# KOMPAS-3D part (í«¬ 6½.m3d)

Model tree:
1. Эскиз:1
2. Операция выдавливания:1
     Расстояние 1 = 3
3. Эскиз:2
4. Операция выдавливания:2
     Расстояние 1 = 78
5. Эскиз:3
6. Операция выдавливания:3
     Расстояние 1 = 3
7. Эскиз:4
8. Операция выдавливания:4
     Расстояние 1 = 4
9. Эскиз:5
10. Операция выдавливания:5
     Расстояние 1 = 4
11. Эскиз:6
12. Вырезать элемент выдавливания:1
     Расстояние 1 = 18.7
13. Эскиз:7
14. Вырезать элемент выдавливания:2
     Расстояние 1 = 118.7
